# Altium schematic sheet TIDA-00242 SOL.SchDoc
size 431 x 279 mm; Date: Not shown in title block; ApprovedBy: Not shown in title block; CheckedBy: Not shown in title block; Author: Not shown in title block; CompanyName: Not shown in title block; Engineer: Not shown in title block; Organization: Not shown in title block; Address1: Not shown in title block; Address2: Not shown in title block; Address3: Not shown in title block; Address4: Not shown in title block; DocumentNumber: 1; Revision: Use project parameter SCH_Rev; SheetNumber: 1; SheetTotal: 1; PageSetup: Record=PageOptions|CenterHorizontal=True|CenterVertical=True|PrintScale=1.00|XCorrection=1.00|YCorrection=1.00|PrintKind=0|BorderSize=5000000|LeftOffset=0|BottomOffset=0|Orientation=2|PaperLength=1000|PaperWidth=1000|Scale=100|PaperSource=15|PrintQuality=600|MediaType=1|DitherType=10|PaperKind=Letter|PrintScaleMode=1
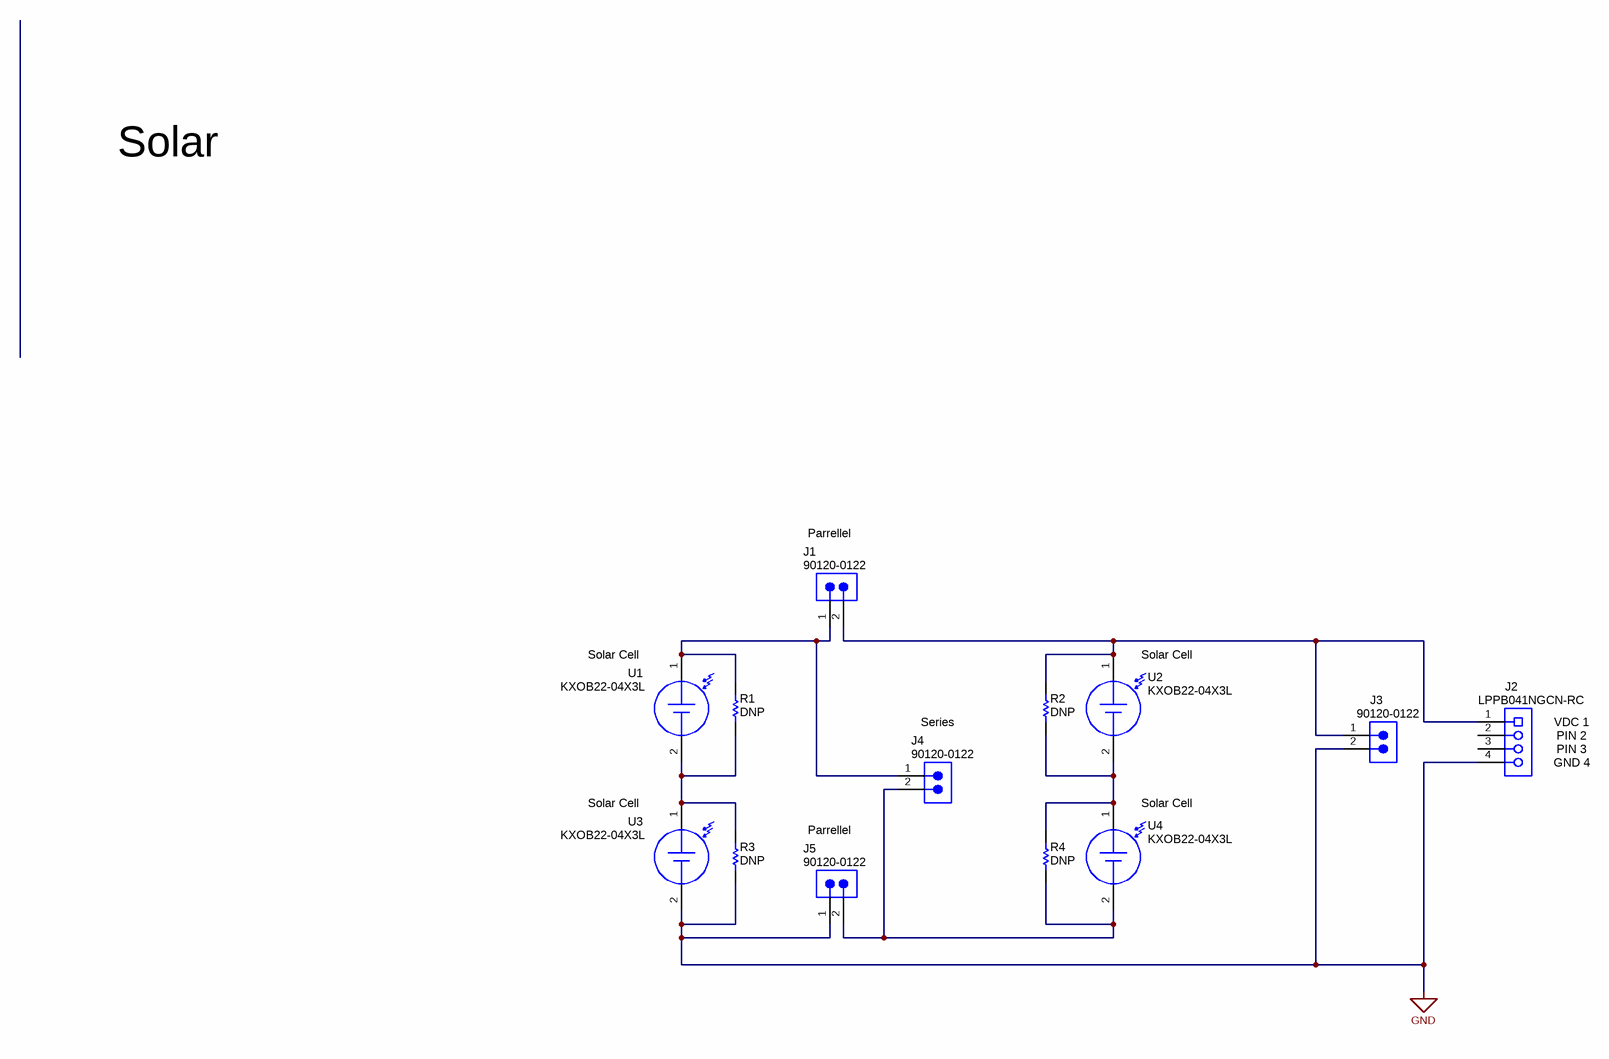
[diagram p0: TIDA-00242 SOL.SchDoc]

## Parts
J1  90120-0122  [CONN_90120-0122]
J2  LPPB041NGCN-RC  [Sullins_LPPB041NGCN]
J3  90120-0122  [CONN_90120-0122]
J4  90120-0122  [CONN_90120-0122]
J5  90120-0122  [CONN_90120-0122]
R1  value DNP  [0805_HV]  (hidden comment: CRCW08050000Z0EA)
R2  value DNP  [0805_HV]  (hidden comment: CRCW08050000Z0EA)
R3  value DNP  [0805_HV]  (hidden comment: CRCW08050000Z0EA)
R4  value DNP  [0805_HV]  (hidden comment: CRCW08050000Z0EA)
U1  KXOB22-04X3L  [KXOB22-04X3]
U2  KXOB22-04X3L  [KXOB22-04X3]
U3  KXOB22-04X3L  [KXOB22-04X3]
U4  KXOB22-04X3L  [KXOB22-04X3]

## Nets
GND: J2.4 J3.2 J5.1 R3.1 U3.2(-)
NetJ1_1: J1.1 J4.1 R1.2 U1.1(+)
NetJ1_2: J1.2 J2.1 J3.1 R2.2 U2.1(+)
NetJ4_2: J4.2 J5.2 R4.1 U4.2(-)
NetR1_1: R1.1 R3.2 U1.2(-) U3.1(+)
NetR2_1: R2.1 R4.2 U2.2(-) U4.1(+)

Not connected (* = marked no-connect by the designer): J2 2 3

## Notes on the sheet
- Solar
- Parrellel
- (near U1) Solar Cell
- (near U2) Solar Cell
- (near J4) Series
- (near J2) VDC 1
- (near J2) PIN 2
- (near J2) PIN 3
- (near J2) GND 4
- (near U3) Solar Cell
- (near U4) Solar Cell

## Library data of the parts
J1 J3-J5 = 90120-0122: Header, 100mil, 2x1, Tin plated, TH; Manufacturer: Molex; SymbolCreator: a0412235; U/M: EA
J2 = LPPB041NGCN-RC: Receptacle, 50mil, 4x1, R/A, TH; Manufacturer: Sullins Connector Solutions; SymbolCreator: a0411947; U/M: EA
R1-R4 = CRCW08050000Z0EA: RES, 0 ohm, 5%, 0.125W, 0805; Manufacturer: Vishay-Dale; CompType: Resistor; Res_ohm: 0; Value_Code: 0000; Tolerance_%: 5; Power_W: 0.125; VDC_V: 150; TempCo: 200 ppm/C; EIA_Code: E24; U/M: EA
U1-U4 = KXOB22-04X3L: MONOCRYSTALLINE SOLAR CELL, 22MM X 7MM, SMD; Manufacturer: IXYS; SymbolCreator: a0412235; Value: 1.5V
